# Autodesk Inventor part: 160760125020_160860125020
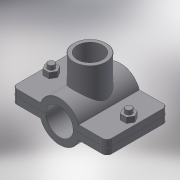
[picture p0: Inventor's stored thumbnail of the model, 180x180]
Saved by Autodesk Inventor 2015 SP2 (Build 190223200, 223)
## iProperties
Created: 2017-05
Part Number: 160760125020_160860125020
Material: Generic
Description: PLASSON SADDLE 125-2"
Document SubType Name: Modeling
Designer: KIM
Density: 1 g/cm^3
Appearance: Default
Author: KIM
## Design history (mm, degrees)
derived "16076.ipt"
feature "Solid1::16076.ipt"
feature "Solid2::16076.ipt"
tag "TaggingFeature1"
body "Solid1"
other parameters: "d0" = 137.5, "d1" = 184, "d2" = 62.5, "d3" = 125, "d4" = 124, "d5" = 0, "d6" = 9.2, "d7" = 184, "d8" = 0.1, "d10" = 0, "d11" = 1.25, "d14" = 73.6528, "d20" = 1.25, "d23" = 1.25, "d36" = 13, "d37" = 10.4, "d38" = 70.5, "d39" = 0, "d40" = 3, "d41" = 5, "d42" = 0, "d43" = 8, "d44" = 3, "d45" = 0, "d46" = 1.25, "d51" = 104, "d52" = 56.656, "d54" = 0, "d57" = 0, "d58" = 135, "d60" = 0, "d62" = 13, "d63" = 10.4, "d66" = 103.2, "d_" = 125, "G_" = 56.656, "A_" = 104, "L_" = 184, "L_1" = 124
